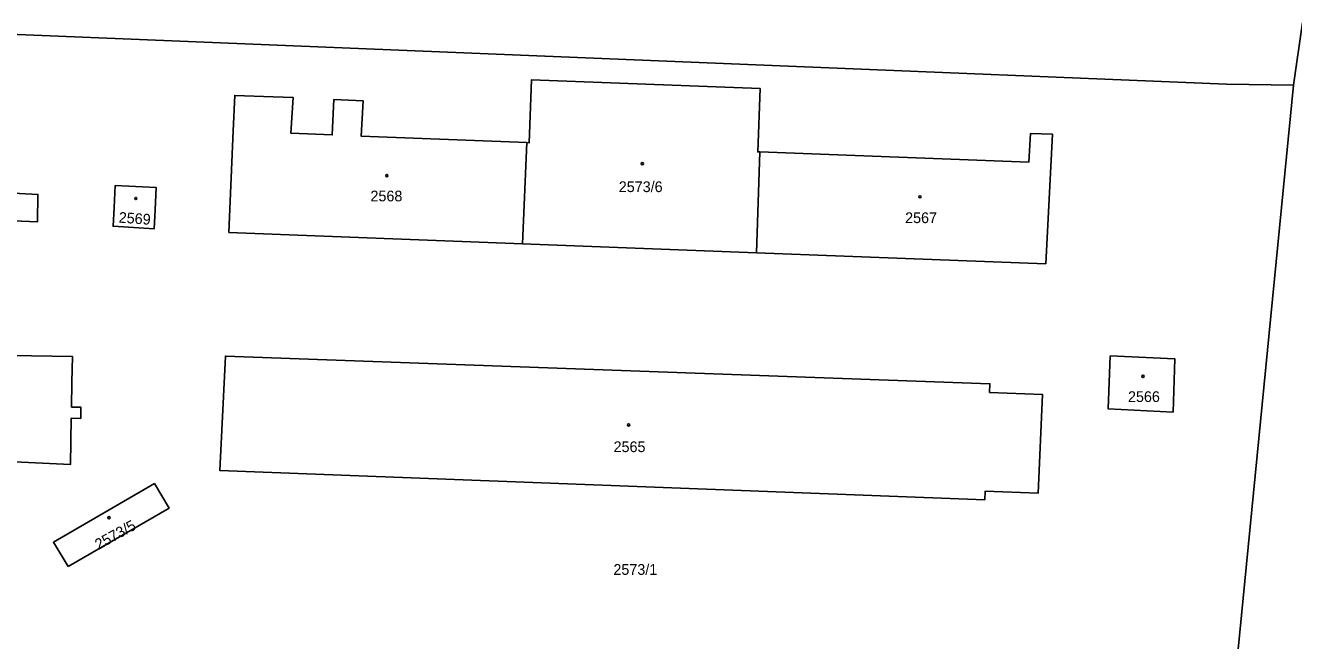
# Model space of a CAD drawing. Extents: x -527335 to -526256, y -1079142 to -1077809.
# Drawn here: x -526804.7 to -526603.7, y -1078250.6 to -1078153 of the extents above; entities that cross this region are included whole.
import ezdxf

# ---------------------------------------------------------------- set-up
doc = ezdxf.new("R2010")
doc.units = 0
for name, color, linetype in [('Vrstva 1', 7, 'Continuous'), ('Vrstva 2', 7, 'Continuous'), ('Vrstva 5', 7, 'Continuous')]:
    doc.layers.add(name, color=color, linetype=linetype)

msp = doc.modelspace()

# ---------------------------------------------------------------- linework, layer by layer
at = {"layer": 'Vrstva 1'}
for p, q in [((-526603.75, -1078162.52), (-526602.3, -1078152.58)), ((-526603.75, -1078162.52), (-526613.4, -1078261.09)), ((-526725.95, -1078187.68), (-526725.26, -1078171.62)), ((-526688.31, -1078173.08), (-526688.86, -1078189.09)), ((-526688.86, -1078189.09), (-526725.95, -1078187.68))]:
    msp.add_line(p, q, dxfattribs=at)
for points in [[(-526830.41, -1078153.45), (-526614.38, -1078162.33), (-526603.75, -1078162.52)], [(-526725.26, -1078171.62), (-526724.85, -1078171.63), (-526724.48, -1078161.66), (-526688.28, -1078163.01), (-526688.63, -1078173.09), (-526688.31, -1078173.08)], [(-526725.26, -1078171.62), (-526751.5, -1078170.58), (-526751.19, -1078164.99), (-526755.84, -1078164.79), (-526756.08, -1078170.39), (-526762.63, -1078170.13), (-526762.29, -1078164.44), (-526765.42, -1078164.34), (-526771.53, -1078164.14), (-526771.77, -1078169.77), (-526772.45, -1078185.87), (-526725.95, -1078187.68)], [(-526688.86, -1078189.09), (-526643, -1078190.85), (-526641.95, -1078170.3), (-526645.42, -1078170.19), (-526645.68, -1078174.71), (-526688.31, -1078173.08)], [(-526811.49, -1078179.37), (-526811.71, -1078183.82), (-526802.81, -1078184.2), (-526802.72, -1078179.83), (-526811.49, -1078179.37)], [(-526784.16, -1078182.26), (-526783.98, -1078178.76), (-526790.46, -1078178.43), (-526790.64, -1078181.9), (-526790.8, -1078184.89), (-526784.31, -1078185.31), (-526784.16, -1078182.26)], [(-526806.6, -1078201.52), (-526817, -1078200.92), (-526827.57, -1078200.61), (-526827.97, -1078221.71), (-526817.58, -1078222.05), (-526807.52, -1078222.2), (-526797.57, -1078222.69), (-526797.43, -1078215.34), (-526795.93, -1078215.37), (-526795.9, -1078213.59), (-526797.39, -1078213.57), (-526797.32, -1078209.62), (-526797.25, -1078205.55), (-526806.95, -1078205.4), (-526806.6, -1078201.52)], [(-526652.64, -1078228.27), (-526652.59, -1078226.89), (-526644.18, -1078227.22), (-526643.53, -1078211.56), (-526651.91, -1078211.25), (-526651.86, -1078209.88), (-526773.01, -1078205.49), (-526773.9, -1078223.63), (-526652.64, -1078228.27)], [(-526632.8, -1078205.43), (-526633.11, -1078213.85), (-526622.82, -1078214.36), (-526622.54, -1078205.94), (-526632.8, -1078205.43)], [(-526797.91, -1078238.86), (-526800.27, -1078235.01), (-526784.26, -1078225.72), (-526781.93, -1078229.6), (-526797.91, -1078238.86)]]:
    msp.add_lwpolyline(points, dxfattribs=at)
at = {"layer": 'Vrstva 5'}
for centre in [(-526706.94, -1078174.96), (-526747.43, -1078176.85), (-526787.21, -1078180.49), (-526662.94, -1078180.22), (-526627.58, -1078208.71), (-526709.1, -1078216.41), (-526791.46, -1078231.12)]:
    msp.add_circle(centre, 0.175, dxfattribs=at)

# ---------------------------------------------------------------- texts
at = {"layer": 'Vrstva 2'}
for s, p in [('2573/6', (-526710.67, -1078179.47)), ('2568', (-526750.02, -1078180.94)), ('2567', (-526665.29, -1078184.39)), ('2566', (-526629.97, -1078212.77)), ('2565', (-526711.49, -1078220.72)), ('2573/1', (-526711.52, -1078240.19))]:
    msp.add_text(s, height=1.7, dxfattribs=at).set_placement(p)
for s, rotation, p in [('2569', 356, (-526789.96, -1078184.31)), ('2573/5', 29, (-526793.1, -1078236.25))]:
    msp.add_text(s, height=1.7, rotation=rotation, dxfattribs=at).set_placement(p)

doc.saveas('drawing.dxf')
